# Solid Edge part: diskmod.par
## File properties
Author: Deepak Maini
Template: NORMENG.PAR
Last saved by: MYPC
Revision: 5
Application: Solid Edge
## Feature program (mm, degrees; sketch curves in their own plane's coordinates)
sketch for "unnamed Protrusion 1" plane through (0, 0, 0) normal (0, 0, 1) x-axis (1, 0, 0)
  line (-25.2008, 3.175) -> (-20.6375, 3.175)
  arc centre (-20.6375, 0) radius 3.175 from (-20.6375, 3.175) to (-20.6375, -3.175) cw
  line (-25.2008, -3.175) -> (-20.6375, -3.175)
  arc centre (0, 0) radius 25.4 from (-3.175, -25.2008) to (-25.2008, -3.175) cw
  line (-3.175, -25.2008) -> (-3.175, -20.6375)
  arc centre (0, -20.6375) radius 3.175 from (-3.175, -20.6375) to (3.175, -20.6375) cw
  line (3.175, -25.2008) -> (3.175, -20.6375)
  arc centre (0, 0) radius 25.4 from (25.2008, -3.175) to (3.175, -25.2008) cw
  line (25.2008, -3.175) -> (20.6375, -3.175)
  arc centre (20.6375, 0) radius 3.175 from (20.6375, -3.175) to (20.6375, 3.175) cw
  line (25.2008, 3.175) -> (20.6375, 3.175)
  arc centre (0, 0) radius 25.4 from (3.175, 25.2008) to (25.2008, 3.175) cw
  line (3.175, 25.2008) -> (3.175, 20.6375)
  arc centre (0, 20.6375) radius 3.175 from (3.175, 20.6375) to (-3.175, 20.6375) cw
  line (-3.175, 25.2008) -> (-3.175, 20.6375)
  arc centre (0, 0) radius 25.4 from (-25.2008, 3.175) to (-3.175, 25.2008) cw
extrude "unnamed Protrusion 1" add finite 3.175 along +normal
sketch for "unnamed Hole 1" plane through (0, 0, 3.175) normal (0, 0, 1) x-axis (1, 0, 0)
  hole centre (0, 0) bore radius 12.7
hole "unnamed Hole 1" through
sketch for "unnamed Protrusion 2" plane through (0, 0, 3.175) normal (0, 0, 1) x-axis (1, 0, 0)
extrude "unnamed Protrusion 2" add finite 15.875 along +normal
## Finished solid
Body 1: solid body, 25 faces, 62 edges, 40 vertices.
  Faces by surface: plane 16, cylinder 9
  Edges by curve: line 44, circle 18
Bounding box of the edges (mm): 50.402 x 50.402 x 19.050, from (-25.2008, -25.2008, 0) to (25.2008, 25.2008, 19.05).
Cylindrical faces by radius (mm): R3.175 x4, R12.7 x1, R25.4 x4
Planar faces by outward normal: +x 3, +y 3, +z 2, -x 3, -y 3, -z 2
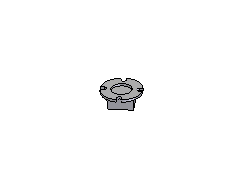
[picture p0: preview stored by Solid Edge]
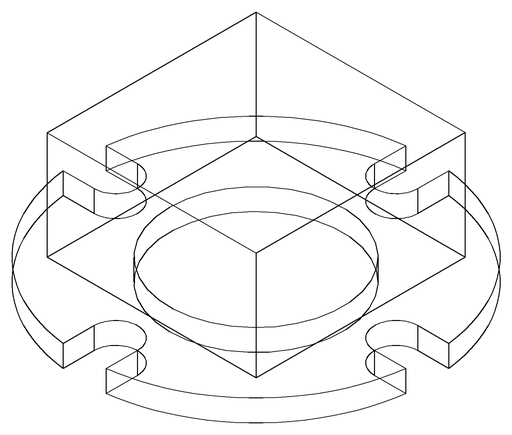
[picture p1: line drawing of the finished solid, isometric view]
